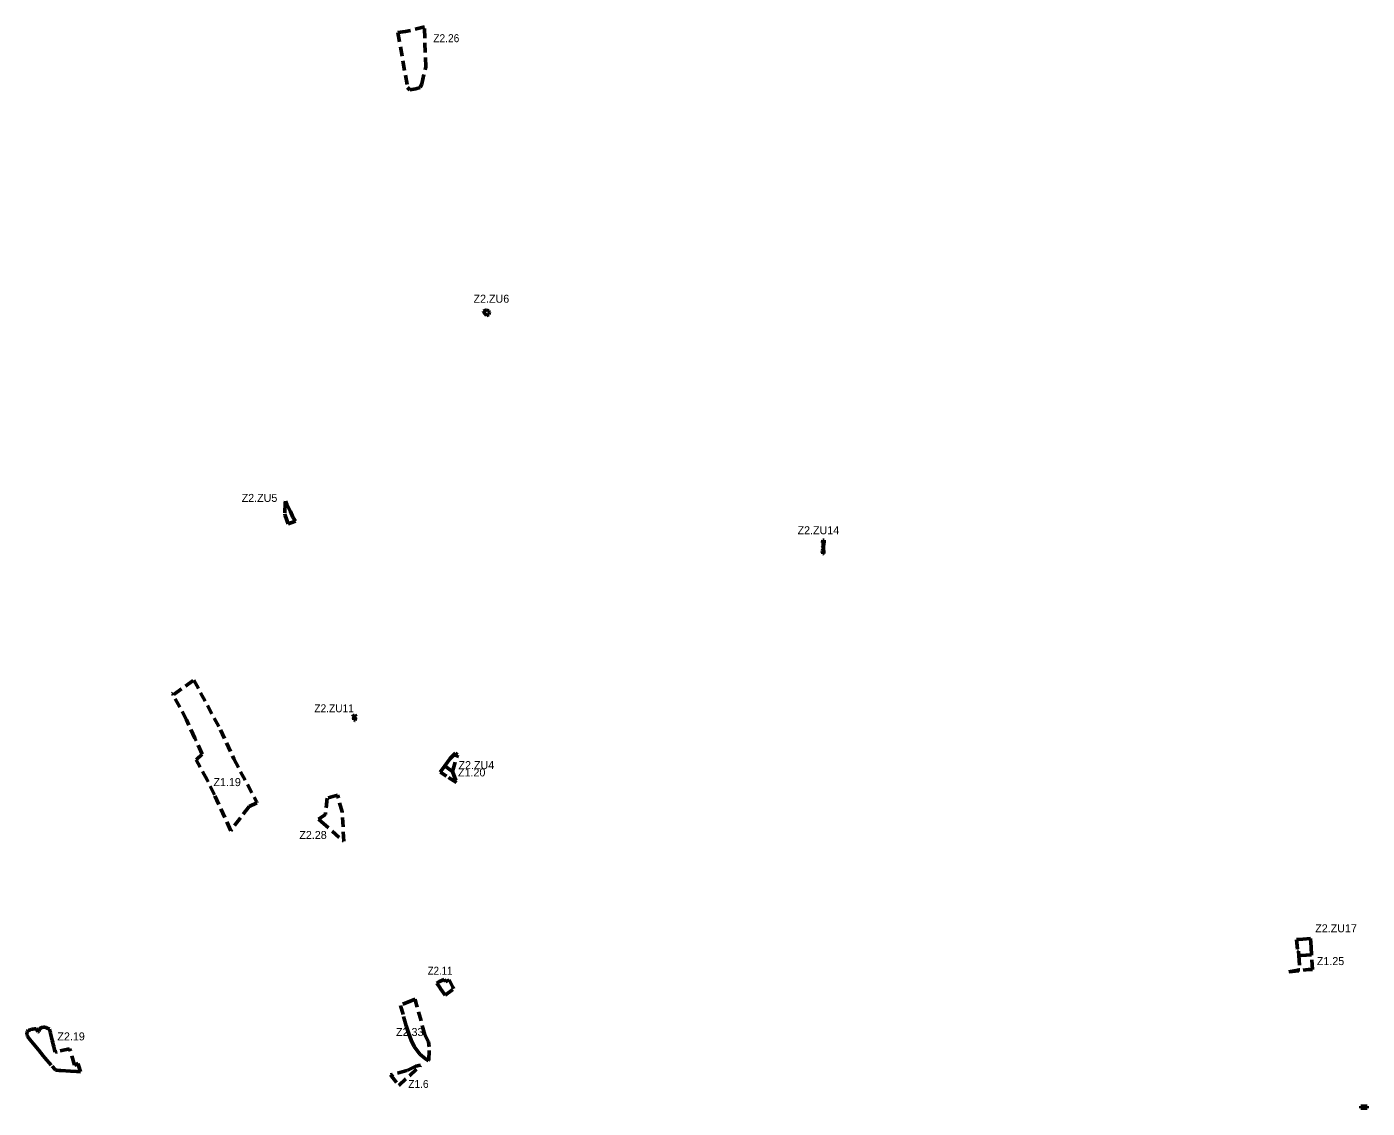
# Model space of a CAD drawing. Extents: x -650368 to -643203, y -1074215 to -1066658.
# Drawn here: x -646793 to -643276, y -1070330 to -1067493 of the extents above; entities that cross this region are included whole.
import ezdxf
from ezdxf.enums import TextEntityAlignment as Align

# ---------------------------------------------------------------- set-up
doc = ezdxf.new("R2010")
doc.units = 0
doc.header["$LTSCALE"] = 8.4
doc.linetypes.add('MEDIUM_DASHED', pattern=[4.5, 3, -1.5])
doc.layers.add('57', color=7, linetype='MEDIUM_DASHED', lineweight=40)
doc.layers.add('58', color=7, linetype='MEDIUM_DASHED', lineweight=53)
doc.layers.add('60', color=7, linetype='Continuous')
doc.layers.add('61', color=7, linetype='Continuous')

msp = doc.modelspace()

# ---------------------------------------------------------------- linework, layer by layer
at = {"layer": '57', "lineweight": 53}
for points in [[(-646410.74, -1069242.8), (-646409.21, -1069241.71), (-646407.33, -1069245.03), (-646354.82, -1069206.96), (-646284.98, -1069337.17), (-646249.6, -1069413.93), (-646190.68, -1069525.54), (-646189.17, -1069528.74), (-646209.9, -1069538.5), (-646258.086, -1069602.285), (-646300.42, -1069507.93), (-646319.61, -1069468.58), (-646348.36, -1069416.16), (-646332.84, -1069401.02), (-646351.69, -1069359.26), (-646373.91, -1069311.42), (-646408.81, -1069246.1)], [(-645694.21, -1069433.78), (-645678.454, -1069444.783), (-645675.91, -1069446.56), (-645665.58, -1069475.61), (-645692.107, -1069459.043), (-645706.8, -1069449.7), (-645708.48, -1069448.63), (-645696.45, -1069432.21)], [(-643481.78, -1069972.39), (-643430.64, -1069966.78), (-643419.43, -1069966.34), (-643422.2, -1069927.68), (-643455.292, -1069930.059), (-643452.63, -1069967.09), (-643455.6, -1069967.63), (-643458.57, -1069968.17), (-643468.026, -1069969.889)], [(-645838.53, -1070243.19), (-645816.9, -1070270.96), (-645760.05, -1070217.79), (-645772.08, -1070220.39), (-645795.85, -1070231.81), (-645833.92, -1070241.96)]]:
    msp.add_lwpolyline(points, close=True, dxfattribs=at)
at = {"layer": '58'}
for points in [[(-645819.48, -1067507.57), (-645793.94, -1067651.61), (-645788.395, -1067658.038), (-645782.72, -1067657.28), (-645772.13, -1067655.13), (-645760.67, -1067652.05), (-645756.491, -1067642.479), (-645746.448, -1067597.944), (-645749.67, -1067492.54), (-645786.52, -1067502.4), (-645799.72, -1067504.47)], [(-645594.36, -1068238.9), (-645586.3, -1068235.27), (-645580.62, -1068237.58), (-645578.75, -1068241.63), (-645580.9, -1068247.49), (-645587.06, -1068250.38), (-645590.885, -1068244.738), (-645594.58, -1068239.29)], [(-646110.72, -1068746.41), (-646114.15, -1068737.05), (-646115.07, -1068742.74), (-646115.86, -1068770.5), (-646115.26, -1068775.39), (-646107.5, -1068796.63), (-646088.06, -1068789.6), (-646094.58, -1068779.42), (-646100.92, -1068764.62)], [(-644704.63, -1068875.27), (-644703.98, -1068875.29), (-644701.79, -1068875.14), (-644701.59, -1068867.03), (-644702.51, -1068867.03), (-644702.41, -1068861.69), (-644701.42, -1068861.72), (-644701.38, -1068859.71), (-644702.34, -1068859.68), (-644702.08, -1068847.23), (-644701.42, -1068847.26), (-644701.09, -1068846.91), (-644700.9, -1068839.57), (-644704.8, -1068840.1), (-644705.08, -1068846.84), (-644704.81, -1068847.09), (-644703.68, -1068847.15), (-644704, -1068859.63), (-644704.74, -1068859.69), (-644705.53, -1068860.05), (-644706.03, -1068860.61), (-644705.56, -1068861.19), (-644704.79, -1068861.59), (-644703.94, -1068861.63), (-644704.08, -1068867.01), (-644705.38, -1068867.01), (-644705.95, -1068867.45), (-644706.19, -1068867.95), (-644706.2, -1068868.36), (-644704.91, -1068870.88), (-644704.56, -1068872.46)], [(-645938.32, -1069303.37), (-645935.71, -1069304.85), (-645934.38, -1069306.59), (-645934.21, -1069306.82), (-645934.66, -1069312.34), (-645934.17, -1069312.41), (-645931.98, -1069312.69), (-645931.24, -1069312.79), (-645930.48, -1069306.22), (-645931.2, -1069306.14), (-645931.07, -1069305.08), (-645933.12, -1069305.94), (-645928.65, -1069302.49), (-645932.07, -1069298.43), (-645936.46, -1069301.94)], [(-645675.91, -1069446.56), (-645663.41, -1069402.83), (-645668.61, -1069398.9), (-645678.06, -1069408.54), (-645682.28, -1069412.88), (-645696.45, -1069432.21), (-645694.21, -1069433.78)], [(-646004.7, -1069517.16), (-646009.52, -1069559.6), (-646017.39, -1069564.94), (-646027.49, -1069571.79), (-646020.4, -1069578.04), (-645961.36, -1069630.05), (-645965.36, -1069552.99), (-645977.73, -1069509.11)], [(-643422.204, -1069927.68), (-643423.64, -1069907.59), (-643425.25, -1069885.25), (-643445.37, -1069886.7), (-643461.33, -1069887.84), (-643459.13, -1069918.47), (-643456.14, -1069918.26), (-643455.292, -1069930.059), (-643455.292, -1069930.059), (-643450.3, -1069929.7)], [(-645695.39, -1070034), (-645673.1, -1070016.78), (-645675.24, -1070012.51), (-645681.339, -1070000.33), (-645684.59, -1069993.87), (-645689.84, -1069996.37), (-645694.8, -1069998.22), (-645697.59, -1069992.31), (-645710.43, -1069998.39), (-645717.36, -1070002.12), (-645709.434, -1070013.522), (-645706.41, -1070018.01)], [(-646784.13, -1070124.41), (-646787, -1070125.38), (-646788.77, -1070126.26), (-646789.61, -1070126.79), (-646791.03, -1070128.23), (-646791.64, -1070129), (-646792.11, -1070129.89), (-646792.76, -1070131.79), (-646792.97, -1070133.76), (-646792.84, -1070135.73), (-646792.42, -1070137.71), (-646792.18, -1070138.48), (-646791.84, -1070139.56), (-646791.13, -1070141.44), (-646790.86, -1070142.02), (-646790.29, -1070142.85), (-646784.8, -1070149.86), (-646775.93, -1070160.78), (-646762.52, -1070177.24), (-646749.79, -1070193.02), (-646745.61, -1070198.15), (-646726.48, -1070220.46), (-646726.36, -1070220.34), (-646719.7, -1070228.25), (-646717.71, -1070230.56), (-646717.71, -1070230.56), (-646714.42, -1070230.81), (-646708.2, -1070231.25), (-646703.67, -1070231.58), (-646677.99, -1070233.44), (-646662.41, -1070234.57), (-646651.86, -1070235.22), (-646656.96, -1070218.43), (-646658.64, -1070212.77), (-646667.64, -1070217.36), (-646680.61, -1070174.79), (-646680.68, -1070174.5), (-646713.74, -1070182.36), (-646718.8, -1070183.56), (-646721.09, -1070173.94), (-646722.4, -1070168.45), (-646723.4, -1070164.29), (-646724.86, -1070158.17), (-646725.39, -1070155.78), (-646726.17, -1070152.7), (-646728.14, -1070144.51), (-646730.45, -1070134.85), (-646730.97, -1070132.67), (-646731.54, -1070130.28), (-646733.35, -1070122.79), (-646740.92, -1070119.57), (-646743.33, -1070118.51), (-646745.78, -1070117.96), (-646748.31, -1070117.83), (-646753.45, -1070118.63), (-646755.74, -1070119.56), (-646757.76, -1070121.07), (-646759.06, -1070122.6), (-646759.78, -1070124), (-646760.32, -1070125.55), (-646760.5, -1070127.58), (-646760.22, -1070129.42), (-646762.07, -1070129.91), (-646763.9, -1070130.41), (-646763.98, -1070130.1), (-646764, -1070129.86), (-646764.94, -1070127.21), (-646765.19, -1070126.23), (-646765.51, -1070125.28), (-646765.97, -1070124.42), (-646767.38, -1070123), (-646768.25, -1070122.53), (-646769.17, -1070122.15), (-646770.43, -1070121.92), (-646772.19, -1070121.98), (-646777.37, -1070122.79), (-646780.28, -1070123.41)], [(-643293.29, -1070324.84), (-643293.27, -1070330.45), (-643285.64, -1070330.42), (-643276.25, -1070330.39), (-643276.27, -1070324.78), (-643283.69, -1070324.81)]]:
    msp.add_lwpolyline(points, close=True, dxfattribs=at)
for points in [[(-645748.62, -1070137.889), (-645772.853, -1070049.868), (-645774.423, -1070044.167), (-645783.063, -1070047.855), (-645812.76, -1070060.53), (-645804.52, -1070089.63)], [(-645804.52, -1070089.63), (-645797.66, -1070113.88), (-645791.72, -1070133.09), (-645784.83, -1070151.9)], [(-645737.624, -1070169.544), (-645738.79, -1070156.281), (-645748.62, -1070137.889)], [(-645784.83, -1070151.9), (-645776.26, -1070168.94), (-645761.78, -1070188.29), (-645746.73, -1070201.04), (-645739.12, -1070205.9), (-645737.756, -1070204.389), (-645737.624, -1070169.544)]]:
    msp.add_lwpolyline(points, dxfattribs=at)

# ---------------------------------------------------------------- texts
at = {"layer": '60'}
for s, p in [('Z1.19', (-646267.37, -1069485.175)), ('Z1.20', (-645625.728, -1069459.757)), ('Z1.25', (-643372.437, -1069954.895))]:
    msp.add_text(s, height=21, dxfattribs=at).set_placement(p, align=Align.CENTER)
at = {"layer": '60', "width": 0.95}
msp.add_text('Z1.6', height=21, dxfattribs=at).set_placement((-645765.49, -1070277.347), align=Align.CENTER)
at = {"layer": '61'}
for s, width, p in [('Z2.26', 0.95, (-645692.356, -1067532.999)), ('Z2.ZU11', 0.95, (-645986.653, -1069291.46)), ('Z2.11', 0.9, (-645708.736, -1069980.15))]:
    msp.add_text(s, height=21, dxfattribs=dict(at, width=width)).set_placement(p, align=Align.CENTER)
for s, p in [('Z2.ZU6', (-645574.084, -1068216.663)), ('Z2.ZU5', (-646182.477, -1068739.396)), ('Z2.ZU14', (-644716.167, -1068824.275)), ('Z2.ZU4', (-645613.502, -1069440.599)), ('Z2.28', (-646041.997, -1069623.92)), ('Z2.ZU17', (-643357.914, -1069868.835)), ('Z2.19', (-646676.745, -1070152.544)), ('Z2.33', (-645788.185, -1070141.025))]:
    msp.add_text(s, height=21, dxfattribs=at).set_placement(p, align=Align.CENTER)

doc.saveas('drawing.dxf')
